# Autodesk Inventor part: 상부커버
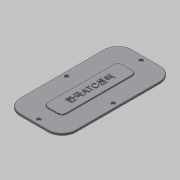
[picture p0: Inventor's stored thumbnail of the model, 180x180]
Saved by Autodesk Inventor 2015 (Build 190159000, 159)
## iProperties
Created: 2016-02
Part Number: 상부커버
Material: 일반
Document SubType Name: Modeling
Designer: mduedu
Density: 1 g/cm^3
Mass: 15.5198 g
Surface Area: 149.263 cm^2
Volume: 15.5198 cm^3
Appearance: 기본값
Author: mduedu
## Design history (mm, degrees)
sketch "스케치1"
  geometry: L1 (30, 60)-(-30, 60); L2 (-30, 60)-(-30, -60); L3 (-30, -60)-(30, -60); L4 (30, -60)-(30, 60); L5 (30, 60)-(-30, -60); L6 (-30, 60)-(30, -60); 1 further point
  constraints: 12 end point, 2 midpoint, 2 parallel, 1 horizontal, 1 perpendicular
  dimensions: "d0" = 60 distance of L2.end L3.end; "d2" = 120 distance of L1.end L2.end
extrude "돌출1" new body sketch "스케치1" distance "d3" = 2; taper "d4" = 0 deg
fillet "모깎기1" dims "d5" = 15
sketch "스케치2"
  geometry: L1 (30, 45)-(30, -45) reference; L2 (15, -60)-(-15, -60) reference; L3 (-30, -45)-(-30, 45) reference; L4 (-15, 60)-(15, 60) reference; L5 (25, 45)-(25, -45); L6 (15, -55)-(-15, -55); L7 (-25, -45)-(-25, 45); L8 (-15, 55)-(15, 55); A1 r 15 centre (15, 45) between (30, 45) and (15, 60) reference; A2 r 15 centre (15, -45) between (15, -60) and (30, -45) reference; A3 r 15 centre (-15, -45) between (-30, -45) and (-15, -60) reference; A4 r 15 centre (-15, 45) between (-15, 60) and (-30, 45) reference; A5 r 10 centre (15, 45) between (25, 45) and (15, 55); A6 r 10 centre (15, -45) between (15, -55) and (25, -45); A7 r 10 centre (-15, -45) between (-25, -45) and (-15, -55); A8 r 10 centre (-15, 45) between (-15, 55) and (-25, 45); 4 further points
  constraints: 8 end point, 8 point on circle, 4 centre point, 4 midpoint, 7 other
  dimensions: "d8" = 5 distance between parallel lines of L7 L3
hole "구멍1" sketch "스케치2" at (0, 55), (25, 0), (0, -55), (-25, 0) diameter "d9" = 4; stored, may be unused: countersink angle "d13" = 90 deg, drill point angle "d15" = 118 deg; dims "d10" = 6, "d11" = 4, "d12" = 2, "d14" = 8
sketch "스케치3"
  geometry: L1 (10, -40)-(-10, -40); L2 (-10, -40)-(-10, 40); L3 (-10, 40)-(10, 40); L4 (10, 40)-(10, -40); L5 (10, -40)-(-10, 40); L6 (-10, -40)-(10, 40); 1 further point
  constraints: 12 end point, 2 midpoint, 2 parallel, 1 horizontal, 1 perpendicular
  dimensions: "d16" = 80 distance of L1.end L2.end; "d18" = 20 distance of L2.end L3.end
extrude "돌출2" join sketch "스케치3" distance "d19" = 1; taper "d20" = 0 deg
fillet "모깎기2" dims "d21" = 5
fillet "모깎기3" dims "d22" = 0.3
fillet "모깎기4" dims "d23" = 0.3
sketch "스케치4"
  geometry: 2 further points
  constraints: 1 coincident, 1 other
feature "엠보싱1" sketch "스케치4" dims "d0" = 60, "d2" = 120, "d8" = 5, "d24" = 0.5, "d25" = 0
node "솔리드1"
node "절단 모서리 투영1"
